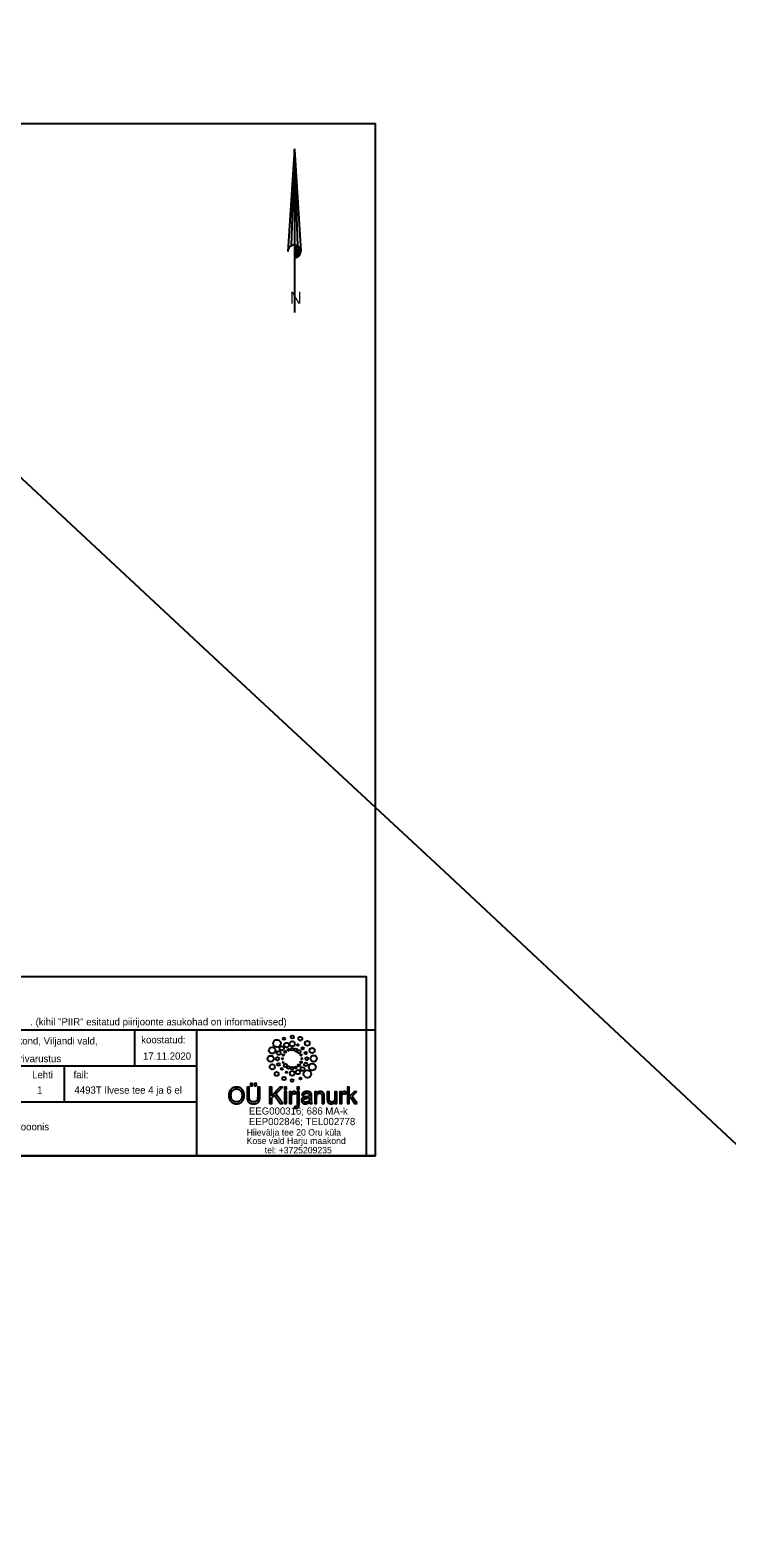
# Model space of a CAD drawing. Extents: x 593727 to 603084, y 6472047 to 6482364.
# Drawn here: x 596085.2 to 596182, y 6473905.8 to 6474115.4 of the extents above; entities that cross this region are included whole.
import ezdxf

# ---------------------------------------------------------------- set-up
doc = ezdxf.new("R2010")
doc.units = 0
doc.layers.add('PIIR', color=7, linetype='Continuous')
doc.layers.add('VORMISTUS', color=7, linetype='Continuous')

msp = doc.modelspace()

# ---------------------------------------------------------------- linework, layer by layer
at = {"layer": 'PIIR'}
msp.add_lwpolyline([(596304.84, 6474319.77), (596309.61, 6474316.56), (596370.38, 6474275.51), (596394.29, 6474258.35), (596451.57, 6474217.25), (596374.59, 6474098.73), (596242.1, 6473905.8), (596181.4, 6473962.34), (596142.83, 6473998.36), (596111.35, 6474027.57), (596079.95, 6474056.82), (596046.92, 6474087.6), (596042.44, 6474091.78), (596034.96, 6474098.69), (596058.46, 6474116.05), (596108.16, 6474156.64), (596298.85, 6474323.82)], close=True, dxfattribs=at)
at = {"layer": 'VORMISTUS'}
for p, q in [((596040.95, 6473976.41), (596133.14, 6473976.41)), ((596099.7, 6473976.41), (596099.7, 6473971.41)), ((596108.3, 6473976.4), (596108.31, 6473958.91)), ((596133.14, 6473976.41), (596133.15, 6473958.91)), ((596040.95, 6473971.41), (596108.3, 6473971.4)), ((596089.89, 6473971.41), (596089.89, 6473966.41)), ((596040.96, 6473966.41), (596108.3, 6473966.41)), ((596040.96, 6473958.91), (596133.14, 6473958.91))]:
    msp.add_line(p, q, dxfattribs=at)
for points in [[(595935.65, 6473958.91), (595935.65, 6474102.41), (596133.15, 6474102.41), (596133.15, 6473958.91)], [(596131.91, 6473958.91), (596040.96, 6473958.91), (596040.96, 6473983.82), (596131.91, 6473983.82)]]:
    msp.add_lwpolyline(points, close=True, dxfattribs=at)
for points in [[(596121.91, 6474098.88), (596121.01, 6474084.62)], [(596121.91, 6474098.78), (596121.49, 6474085.41)], [(596121.9, 6474098.83), (596122.37, 6474085.38)], [(596121.91, 6474098.88), (596121.91, 6474076.13)], [(596121.91, 6474098.77), (596122.8, 6474084.64)], [(596121.91, 6474085.51), (596121.95, 6474085.51)], [(596121.91, 6474085.51), (596121.93, 6474085.51)], [(596121.91, 6474085.41), (596122.34, 6474085.41)], [(596121.91, 6474085.3), (596122.48, 6474085.3)], [(596121.91, 6474085.2), (596122.57, 6474085.2)], [(596121.91, 6474085.1), (596122.65, 6474085.1)], [(596121.91, 6474084.99), (596122.71, 6474084.99)], [(596121.98, 6474083.74), (596121.98, 6474085.5)], [(596122.08, 6474083.76), (596122.08, 6474085.49)], [(596122.19, 6474083.77), (596122.19, 6474085.46)], [(596122.29, 6474083.82), (596122.29, 6474085.42)], [(596122.39, 6474083.88), (596122.39, 6474085.38)], [(596122.49, 6474083.96), (596122.49, 6474085.29)], [(596122.6, 6474084.06), (596122.6, 6474085.17)], [(596122.7, 6474084.23), (596122.7, 6474085.03)], [(596121.9, 6474083.76), (596122.1, 6474083.76)], [(596121.91, 6474084.89), (596122.75, 6474084.89)], [(596121.91, 6474084.79), (596122.78, 6474084.79)], [(596121.91, 6474084.68), (596122.79, 6474084.68)], [(596121.91, 6474084.58), (596122.8, 6474084.58)], [(596121.91, 6474084.48), (596122.78, 6474084.48)], [(596121.91, 6474084.38), (596122.76, 6474084.38)], [(596121.91, 6474084.27), (596122.72, 6474084.27)], [(596121.91, 6474084.17), (596122.67, 6474084.17)], [(596121.91, 6474084.07), (596122.6, 6474084.07)], [(596121.91, 6474083.96), (596122.5, 6474083.96)], [(596121.91, 6474083.86), (596122.36, 6474083.86)], [(596115.64, 6473967.12), (596115.64, 6473968.42), (596115.34, 6473968.42), (596115.34, 6473967.12)], [(596116.08, 6473968.63), (596116.08, 6473968.94), (596115.8, 6473968.94), (596115.8, 6473968.63), (596116.08, 6473968.63)], [(596116.65, 6473968.63), (596116.65, 6473968.94), (596116.37, 6473968.94), (596116.37, 6473968.63), (596116.65, 6473968.63)], [(596117.11, 6473967.12), (596117.11, 6473968.42), (596116.81, 6473968.42), (596116.81, 6473967.12)], [(596120.32, 6473966.17), (596119.34, 6473967.51), (596120.28, 6473968.42), (596119.88, 6473968.42), (596118.76, 6473967.3), (596118.76, 6473968.42), (596118.46, 6473968.42), (596118.46, 6473966.17), (596118.76, 6473966.17), (596118.76, 6473966.95), (596119.13, 6473967.31), (596119.93, 6473966.17), (596120.32, 6473966.17)], [(596120.82, 6473968.11), (596120.82, 6473968.42), (596120.54, 6473968.42), (596120.54, 6473968.11), (596120.82, 6473968.11)], [(596120.82, 6473966.17), (596120.82, 6473967.8), (596120.54, 6473967.8), (596120.54, 6473966.17), (596120.82, 6473966.17)], [(596121.49, 6473967.55), (596121.48, 6473967.55), (596121.48, 6473967.8), (596121.23, 6473967.8), (596121.23, 6473966.17), (596121.51, 6473966.17), (596121.51, 6473967.03)], [(596122.02, 6473967.49), (596122.12, 6473967.75)], [(596122.56, 6473968.11), (596122.56, 6473968.42), (596122.29, 6473968.42), (596122.29, 6473968.11), (596122.56, 6473968.11)], [(596122.56, 6473966.08), (596122.56, 6473967.8), (596122.29, 6473967.8), (596122.29, 6473966.09)], [(596124.99, 6473967.57), (596124.99, 6473967.57), (596124.99, 6473967.8), (596124.74, 6473967.8), (596124.74, 6473966.17), (596125.01, 6473966.17), (596125.01, 6473967.06)], [(596126.76, 6473966.9), (596126.76, 6473967.8), (596126.48, 6473967.8), (596126.48, 6473966.79)], [(596127.8, 6473966.17), (596127.8, 6473967.8), (596127.53, 6473967.8), (596127.53, 6473966.93)], [(596128.48, 6473967.55), (596128.47, 6473967.55), (596128.47, 6473967.8), (596128.22, 6473967.8), (596128.22, 6473966.17), (596128.5, 6473966.17), (596128.5, 6473967.03)], [(596129.01, 6473967.49), (596129.11, 6473967.75)], [(596130.63, 6473966.17), (596129.94, 6473967.2), (596130.57, 6473967.8), (596130.21, 6473967.8), (596129.55, 6473967.14), (596129.55, 6473968.42), (596129.28, 6473968.42), (596129.28, 6473966.17), (596129.55, 6473966.17), (596129.55, 6473966.82), (596129.75, 6473967), (596130.29, 6473966.17), (596130.63, 6473966.17)], [(596121.99, 6473965.77), (596121.94, 6473965.54)], [(596122.94, 6473967.33), (596123.21, 6473967.3)], [(596123.8, 6473967.15), (596123.54, 6473967.11)], [(596124.03, 6473966.99), (596124.03, 6473966.89)], [(596124.11, 6473966.17), (596124.4, 6473966.17)], [(596124.31, 6473966.85), (596124.31, 6473967.22)], [(596125.79, 6473967.16), (596125.79, 6473966.17), (596126.07, 6473966.17)], [(596126.07, 6473966.17), (596126.07, 6473967.17)], [(596127.55, 6473966.41), (596127.56, 6473966.41), (596127.56, 6473966.17), (596127.8, 6473966.17)], [(596040.96, 6473958.91), (596133.14, 6473958.91)]]:
    msp.add_lwpolyline(points, dxfattribs=at)
for centre, radius in [((596118.83, 6473973.56), 0.452), ((596119.49, 6473974.52), 0.525), ((596120.16, 6473973.84), 0.301), ((596120.47, 6473975.18), 0.154), ((596120.82, 6473974.29), 0.329), ((596121.61, 6473974.46), 0.362), ((596121.61, 6473975.41), 0.224), ((596121.61, 6473973.73), 0.186), ((596122.39, 6473974.3), 0.11), ((596122.74, 6473975.19), 0.264), ((596123.05, 6473973.86), 0.161), ((596123.72, 6473974.53), 0.336), ((596124.38, 6473973.55), 0.361), ((596118.62, 6473972.39), 0.428), ((596119.56, 6473972.39), 0.221), ((596119.73, 6473973.19), 0.263), ((596119.71, 6473971.6), 0.188), ((596120.26, 6473972.39), 0.0948), ((596120.37, 6473972.9), 0.111), ((596120.37, 6473971.89), 0.0704), ((596120.65, 6473973.35), 0.132), ((596121.1, 6473973.64), 0.15), ((596122.11, 6473973.62), 0.203), ((596122.56, 6473973.36), 0.229), ((596122.85, 6473971.91), 0.12), ((596122.85, 6473972.91), 0.0929), ((596122.95, 6473972.41), 0.0929), ((596123.5, 6473971.61), 0.246), ((596123.49, 6473973.19), 0.173), ((596123.65, 6473972.42), 0.211), ((596124.6, 6473972.42), 0.447), ((596118.84, 6473971.27), 0.358), ((596119.45, 6473970.28), 0.277), ((596120.16, 6473970.97), 0.132), ((596120.48, 6473969.64), 0.242), ((596120.67, 6473971.46), 0.233), ((596120.82, 6473970.52), 0.108), ((596121.11, 6473971.17), 0.19), ((596121.62, 6473970.37), 0.339), ((596121.61, 6473971.07), 0.19), ((596122.12, 6473971.17), 0.146), ((596122.4, 6473970.54), 0.303), ((596122.56, 6473971.47), 0.146), ((596122.75, 6473969.63), 0.139), ((596123.06, 6473970.97), 0.269), ((596123.73, 6473970.28), 0.534), ((596124.4, 6473971.26), 0.485), ((596121.61, 6473969.39), 0.187)]:
    msp.add_circle(centre, radius, dxfattribs=at)
msp.add_arc((596121.91, 6474084.62), 0.894, 270.3348, 180.6244, dxfattribs=at)
for points in [[(596113.09, 6473968.14), (596112.79, 6473967.82), (596112.79, 6473967.27)], [(596113.87, 6473968.46), (596113.39, 6473968.46), (596113.09, 6473968.14)], [(596113.1, 6473967.26), (596113.1, 6473967.74), (596113.32, 6473967.97)], [(596113.32, 6473967.97), (596113.54, 6473968.2), (596113.87, 6473968.2)], [(596114.64, 6473968.14), (596114.34, 6473968.46), (596113.87, 6473968.46)], [(596113.87, 6473968.2), (596114.2, 6473968.2), (596114.42, 6473967.97)], [(596114.42, 6473967.97), (596114.64, 6473967.73), (596114.64, 6473967.29)], [(596114.95, 6473967.29), (596114.95, 6473967.82), (596114.64, 6473968.14)], [(596121.84, 6473967.84), (596121.62, 6473967.84), (596121.49, 6473967.55)], [(596122.12, 6473967.75), (596121.98, 6473967.84), (596121.84, 6473967.84)], [(596123.17, 6473967.71), (596122.99, 6473967.58), (596122.94, 6473967.33)], [(596123.68, 6473967.84), (596123.36, 6473967.84), (596123.17, 6473967.71)], [(596123.36, 6473967.54), (596123.46, 6473967.61), (596123.64, 6473967.61)], [(596123.64, 6473967.61), (596123.78, 6473967.61), (596123.86, 6473967.58)], [(596124.11, 6473967.75), (596123.97, 6473967.84), (596123.68, 6473967.84)], [(596123.86, 6473967.58), (596123.94, 6473967.54), (596123.98, 6473967.49)], [(596124.28, 6473967.54), (596124.25, 6473967.66), (596124.11, 6473967.75)], [(596125.21, 6473967.77), (596125.08, 6473967.7), (596124.99, 6473967.57)], [(596125.51, 6473967.84), (596125.34, 6473967.84), (596125.21, 6473967.77)], [(596125.22, 6473967.54), (596125.33, 6473967.6), (596125.45, 6473967.6)], [(596125.45, 6473967.6), (596125.61, 6473967.6), (596125.7, 6473967.5)], [(596125.76, 6473967.79), (596125.63, 6473967.84), (596125.51, 6473967.84)], [(596125.96, 6473967.65), (596125.89, 6473967.74), (596125.76, 6473967.79)], [(596126.05, 6473967.45), (596126.03, 6473967.56), (596125.96, 6473967.65)], [(596128.83, 6473967.84), (596128.61, 6473967.84), (596128.48, 6473967.55)], [(596129.11, 6473967.75), (596128.97, 6473967.84), (596128.83, 6473967.84)], [(596112.79, 6473967.27), (596112.79, 6473966.79), (596113.09, 6473966.46)], [(596113.09, 6473966.46), (596113.38, 6473966.13), (596113.87, 6473966.13)], [(596113.31, 6473966.63), (596113.1, 6473966.87), (596113.1, 6473967.26)], [(596113.87, 6473966.39), (596113.53, 6473966.39), (596113.31, 6473966.63)], [(596114.42, 6473966.63), (596114.21, 6473966.39), (596113.87, 6473966.39)], [(596113.87, 6473966.13), (596114.34, 6473966.13), (596114.64, 6473966.45)], [(596114.64, 6473967.29), (596114.63, 6473966.87), (596114.42, 6473966.63)], [(596114.64, 6473966.45), (596114.95, 6473966.77), (596114.95, 6473967.29)], [(596115.34, 6473967.12), (596115.34, 6473966.92), (596115.36, 6473966.77)], [(596115.36, 6473966.77), (596115.39, 6473966.61), (596115.47, 6473966.46)], [(596115.47, 6473966.46), (596115.56, 6473966.32), (596115.74, 6473966.22)], [(596115.66, 6473966.77), (596115.64, 6473966.92), (596115.64, 6473967.12)], [(596115.82, 6473966.51), (596115.69, 6473966.63), (596115.66, 6473966.77)], [(596115.74, 6473966.22), (596115.93, 6473966.13), (596116.23, 6473966.13)], [(596116.2, 6473966.4), (596115.94, 6473966.4), (596115.82, 6473966.51)], [(596116.6, 6473966.49), (596116.46, 6473966.4), (596116.2, 6473966.4)], [(596116.23, 6473966.13), (596116.54, 6473966.13), (596116.72, 6473966.24)], [(596116.77, 6473966.73), (596116.73, 6473966.58), (596116.6, 6473966.49)], [(596116.72, 6473966.24), (596116.91, 6473966.34), (596116.99, 6473966.49)], [(596116.81, 6473967.12), (596116.81, 6473966.88), (596116.77, 6473966.73)], [(596116.99, 6473966.49), (596117.07, 6473966.65), (596117.09, 6473966.8)], [(596117.09, 6473966.8), (596117.11, 6473966.95), (596117.11, 6473967.12)], [(596121.51, 6473967.03), (596121.51, 6473967.28), (596121.59, 6473967.41)], [(596121.59, 6473967.41), (596121.67, 6473967.55), (596121.82, 6473967.55)], [(596121.82, 6473967.55), (596121.92, 6473967.55), (596122.02, 6473967.49)], [(596121.94, 6473965.54), (596122.04, 6473965.51), (596122.15, 6473965.51)], [(596122.12, 6473965.75), (596122.07, 6473965.75), (596121.99, 6473965.77)], [(596122.25, 6473965.81), (596122.21, 6473965.75), (596122.12, 6473965.75)], [(596122.15, 6473965.51), (596122.34, 6473965.51), (596122.43, 6473965.6)], [(596122.29, 6473966.09), (596122.29, 6473965.87), (596122.25, 6473965.81)], [(596122.43, 6473965.6), (596122.52, 6473965.69), (596122.54, 6473965.81)], [(596122.54, 6473965.81), (596122.56, 6473965.92), (596122.56, 6473966.08)], [(596123.04, 6473966.94), (596122.9, 6473966.8), (596122.9, 6473966.6)], [(596122.9, 6473966.6), (596122.9, 6473966.39), (596123.05, 6473966.26)], [(596123.54, 6473967.11), (596123.18, 6473967.07), (596123.04, 6473966.94)], [(596123.05, 6473966.26), (596123.19, 6473966.13), (596123.45, 6473966.13)], [(596123.19, 6473966.61), (596123.19, 6473966.83), (596123.5, 6473966.87)], [(596123.28, 6473966.42), (596123.19, 6473966.5), (596123.19, 6473966.61)], [(596123.21, 6473967.3), (596123.25, 6473967.48), (596123.36, 6473967.54)], [(596123.52, 6473966.35), (596123.36, 6473966.35), (596123.28, 6473966.42)], [(596123.45, 6473966.13), (596123.77, 6473966.13), (596124.05, 6473966.37)], [(596123.5, 6473966.87), (596123.82, 6473966.91), (596124.03, 6473966.99)], [(596123.88, 6473966.47), (596123.72, 6473966.35), (596123.52, 6473966.35)], [(596124.03, 6473967.2), (596123.94, 6473967.17), (596123.8, 6473967.15)], [(596124.03, 6473966.89), (596124.03, 6473966.59), (596123.88, 6473966.47)], [(596123.98, 6473967.49), (596124.02, 6473967.43), (596124.03, 6473967.38)], [(596124.03, 6473967.38), (596124.03, 6473967.33), (596124.03, 6473967.2)], [(596124.05, 6473966.37), (596124.07, 6473966.25), (596124.11, 6473966.17)], [(596124.31, 6473967.22), (596124.31, 6473967.42), (596124.28, 6473967.54)], [(596124.32, 6473966.4), (596124.31, 6473966.51), (596124.31, 6473966.85)], [(596124.4, 6473966.17), (596124.34, 6473966.28), (596124.32, 6473966.4)], [(596125.01, 6473967.06), (596125.01, 6473967.26), (596125.06, 6473967.37)], [(596125.06, 6473967.37), (596125.11, 6473967.48), (596125.22, 6473967.54)], [(596125.7, 6473967.5), (596125.79, 6473967.41), (596125.79, 6473967.16)], [(596126.07, 6473967.17), (596126.07, 6473967.35), (596126.05, 6473967.45)], [(596126.48, 6473966.79), (596126.48, 6473966.57), (596126.53, 6473966.43)], [(596126.53, 6473966.43), (596126.58, 6473966.29), (596126.72, 6473966.21)], [(596126.72, 6473966.21), (596126.87, 6473966.13), (596127.04, 6473966.13)], [(596126.78, 6473966.59), (596126.76, 6473966.68), (596126.76, 6473966.9)], [(596126.89, 6473966.43), (596126.8, 6473966.49), (596126.78, 6473966.59)], [(596127.09, 6473966.37), (596126.97, 6473966.37), (596126.89, 6473966.43)], [(596127.04, 6473966.13), (596127.36, 6473966.13), (596127.55, 6473966.41)], [(596127.39, 6473966.48), (596127.25, 6473966.37), (596127.09, 6473966.37)], [(596127.53, 6473966.93), (596127.53, 6473966.59), (596127.39, 6473966.48)], [(596128.5, 6473967.03), (596128.5, 6473967.28), (596128.58, 6473967.41)], [(596128.58, 6473967.41), (596128.66, 6473967.55), (596128.81, 6473967.55)], [(596128.81, 6473967.55), (596128.91, 6473967.55), (596129.01, 6473967.49)]]:
    msp.add_open_spline(points, degree=2, dxfattribs=at)

# ---------------------------------------------------------------- texts
msp.add_text('N', height=1.67, dxfattribs=at).set_placement((596121.29, 6474077.33))
for s, height, rotation, p in [('. (kihil "PIIR" esitatud piirijoonte asukohad on informatiivsed)', 1, 359.9946, (596085.19, 6473977.03)), ('Viljandi maakond, Viljandi vald,', 0.9997, 359.9974, (596076.13, 6473974.38)), ('koostatud:', 1, 359.9974, (596100.62, 6473974.53)), ('Ilvese tee 4 ja 6 elektrivarustus', 0.9997, 359.9974, (596071.13, 6473971.91)), ('17.11.2020', 1, 359.9974, (596100.86, 6473972.27)), ('Lehti', 1, 359.9974, (596085.44, 6473969.67)), ('fail:', 1, 359.9974, (596091.21, 6473969.67)), ('1', 1, 359.9974, (596086.14, 6473967.54)), ('4493T Ilvese tee 4 ja 6 el', 0.9997, 359.9974, (596091.33, 6473967.54)), ('EEG000316; 686 MA-k', 0.9997, 359.9974, (596115.59, 6473964.63)), ('Elektrirajatise teostusjooonis', 0.9997, 359.9974, (596070.87, 6473962.44)), ('EEP002846; TEL002778', 0.9997, 359.9974, (596115.59, 6473963.17)), ('Hiievälja tee 20 Oru küla', 0.8997, 359.9974, (596115.28, 6473961.71)), ('Kose vald Harju maakond', 0.8997, 359.9974, (596115.28, 6473960.54)), ('tel: +3725209235', 0.8997, 359.9974, (596117.79, 6473959.24))]:
    msp.add_text(s, height=height, rotation=rotation, dxfattribs=at).set_placement(p)

doc.saveas('drawing.dxf')
